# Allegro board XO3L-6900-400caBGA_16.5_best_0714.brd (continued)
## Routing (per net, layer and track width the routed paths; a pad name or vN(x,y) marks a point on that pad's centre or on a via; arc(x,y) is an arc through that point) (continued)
PR19B: length 8.2
  TOP w0.102: BGA.R20 v1(28.32,16.32)
  L3_SIGNAL w0.102: v1(28.32,16.32) 28.57,16.32 28.68,16.43 35.86,16.43
PR19C: length 12.5
  TOP w0.102: BGA.M15 v1(24.32,19.52)
  L4_SIGNAL w0.102: 35.88,19.48 27.21,19.48 26.84,19.11 24.73,19.11 v1(24.32,19.52)
PR19D: length 13.2
  TOP w0.102: BGA.M14 v1(23.52,19.52)
  L4_SIGNAL w0.102: v1(23.52,19.52) 23.92,19.92 26.97,19.92 27.22,19.66 35.89,19.66
PR21A: length 12.3
  TOP w0.102: BGA.N16 v1(25.12,18.72)
  L4_SIGNAL w0.102: 35.89,17.32 27.81,17.32 27.62,17.51 25.7,17.51 25.53,17.68 25.53,18.31 v1(25.12,18.72)
PR21B: length 9.6
  TOP w0.102: BGA.R19 v1(27.52,16.32)
  L4_SIGNAL w0.102: v1(27.52,16.32) 27.52,16.84 27.82,17.14 35.89,17.14
PR21C: length 8
  TOP w0.102: 35.88,15.7 28.39,15.7 28.17,15.92 BGA.T20
PR21D: length 8.9
  TOP w0.102: BGA.T19 27.39,15.92 27.79,15.53 35.88,15.53
PR22A: length 8.2
  TOP w0.102: BGA.U20 v1(28.32,14.72)
  L3_SIGNAL w0.102: v1(28.32,14.72) 28.7,14.72 28.8,14.61 35.86,14.61
PR22B: length 13.8
  TOP w0.102: BGA.P17 v1(25.92,17.92)
  L3_SIGNAL w0.102: v1(25.92,17.92) 25.92,17.69 26.32,17.3 26.32,14.51 26.5,14.32 28.69,14.32 28.8,14.44 35.86,14.44
PR22C: length 10
  TOP w0.102: BGA.T18 v1(26.72,15.52)
  L3_SIGNAL w0.102: v1(26.72,15.52) 26.99,15.25 27.13,15.25 27.49,15.61 35.86,15.61
PR22D: length 9.8
  TOP w0.102: BGA.U19 v1(27.52,14.72)
  L3_SIGNAL w0.102: v1(27.52,14.72) 27.25,14.99 27.25,15.13 27.56,15.44 35.86,15.44
PR23A: length 10.2
  TOP w0.102: BGA.V20 v1(28.32,13.92)
  L4_SIGNAL w0.102: 27.31,4.75 27.31,12.91 v1(28.32,13.92)
PR23B: length 14.8
  TOP w0.102: BGA.P16 v1(25.12,17.92)
  L4_SIGNAL w0.102: 27.13,4.75 27.13,12.89 26.32,13.71 26.32,15.62 26.02,15.92 25.71,15.92 25.53,16.11 25.53,17.25 25.12,17.66 v1(25.12,17.92)
PR23C: length 12.4
  TOP w0.102: BGA.N15 v1(24.32,18.72)
  BOTTOM w0.102: 35.88,18.06 28.83,18.06 28.57,18.32 24.72,18.32 v1(24.32,18.72)
PR23D: length 13.9
  TOP w0.102: BGA.N14 v1(23.52,18.72)
  BOTTOM w0.102: v1(23.52,18.72) 23.93,18.31 23.93,17.7 24.12,17.52 28.48,17.52 28.83,17.87 35.88,17.87
PR24A: length 11.4
  TOP w0.102: BGA.R17 v1(25.92,17.12)
  L4_SIGNAL w0.102: 35.89,15.88 26.58,15.88 26.32,16.15 26.32,16.72 v1(25.92,17.12)
PR24B: length 10.3
  TOP w0.102: BGA.U18 v1(26.72,14.72)
  L4_SIGNAL w0.102: 35.89,15.71 27.41,15.71 27.22,15.52 27.22,15.22 v1(26.72,14.72)
PR24C: length 14
  TOP w0.102: BGA.P15 v1(24.32,17.92)
  L4_SIGNAL w0.102: 24.23,4.75 24.23,14.19 23.91,14.51 23.91,17.51 v1(24.32,17.92)
PR24D: length 13.2
  TOP w0.102: BGA.R16 v1(25.12,17.12)
  L4_SIGNAL w0.102: 24.41,4.75 24.41,14.19 24.72,14.5 24.72,16.72 v1(25.12,17.12)
PR25A: length 10.7
  TOP w0.102: BGA.V19 v1(27.52,13.92)
  L3_SIGNAL w0.102: v1(27.52,13.92) 26.98,13.38 26.34,13.38 26.23,13.28 26.23,4.75
PR25B: length 12.5
  TOP w0.102: BGA.T17 v1(25.92,16.32)
  L3_SIGNAL w0.102: v1(25.92,16.32) 25.53,15.93 25.53,13.91 26.06,13.38 26.06,4.75
PR25C: length 11.6
  TOP w0.102: BGA.U17 v1(25.92,15.52)
  L4_SIGNAL w0.102: v1(25.92,15.52) 25.52,15.13 25.52,14.38 25.66,14.25 25.66,4.75
PR25D: length 10.6
  TOP w0.102: BGA.V17 v1(25.92,14.72)
  L4_SIGNAL w0.102: v1(25.92,14.72) 25.92,14.34 25.84,14.26 25.84,4.75
PT9A: length 8.9
  TOP w0.102: BGA.B1 12.72,27.39 12.33,27.79 12.33,35.88
PT9B: length 8
  TOP w0.102: 12.5,35.88 12.5,28.39 12.72,28.17 BGA.A1
PT9C: length 13.2
  TOP w0.102: BGA.G7 v1(17.12,23.52)
  L4_SIGNAL w0.102: v1(17.12,23.52) 16.73,23.91 16.73,27.1 17.02,27.4 17.02,35.86
PT9D: length 12.4
  TOP w0.102: BGA.F7 v1(17.12,24.32)
  L4_SIGNAL w0.102: 17.2,35.86 17.2,27.38 17.53,27.05 17.53,24.73 v1(17.12,24.32)
PT10A: length 8.9
  TOP w0.102: BGA.B2 13.52,27.39 13.13,27.79 13.13,35.88
PT10B: length 8
  TOP w0.102: 13.3,35.88 13.3,28.39 13.52,28.17 BGA.A2
PT10C: length 11.6
  TOP w0.102: BGA.E6 v1(16.32,25.12)
  L3_SIGNAL w0.102: 15.61,35.86 15.61,27.35 15.92,27.04 15.92,25.52 v1(16.32,25.12)
PT10D: length 10.8
  TOP w0.102: BGA.D5 v1(15.52,25.92)
  L3_SIGNAL w0.102: v1(15.52,25.92) 15.12,26.32 15.12,27.03 15.44,27.35 15.44,35.86
PT11A: length 8.9
  TOP w0.102: 13.93,35.88 13.93,27.79 14.32,27.39 BGA.B3
PT11B: length 8
  TOP w0.102: 14.1,35.88 14.1,28.39 14.32,28.17 BGA.A3
PT11C: length 10.8
  TOP w0.102: BGA.D6 v1(16.32,25.92)
  BOTTOM w0.102: v1(16.32,25.92) 15.92,26.32 15.92,26.99 16.22,27.28 16.22,35.86
PT11D: length 11.6
  TOP w0.102: BGA.E7 v1(17.12,25.12)
  BOTTOM w0.102: 16.4,35.86 16.4,27.27 16.72,26.95 16.72,25.52 v1(17.12,25.12)
PT12A: length 8.9
  TOP w0.102: 14.73,35.88 14.73,27.79 15.12,27.39 BGA.B4
PT12B: length 8
  TOP w0.102: BGA.A4 15.12,28.17 14.9,28.39 14.9,35.88
PT12C: length 9.8
  TOP w0.102: BGA.C6 v1(16.32,26.72)
  L3_SIGNAL w0.102: v1(16.32,26.72) 16.32,27.06 16.43,27.17 16.43,35.89
PT12D: length 10.7
  TOP w0.102: BGA.D7 v1(17.12,25.92)
  L3_SIGNAL w0.102: 16.6,35.89 16.6,27.16 16.73,27.04 16.73,26.31 v1(17.12,25.92)
PT13A: length 8.9
  TOP w0.102: 15.53,35.88 15.53,27.79 15.92,27.39 BGA.B5
PT13B: length 8
  TOP w0.102: BGA.A5 15.92,28.17 15.7,28.39 15.7,35.88
PT13C: length 13.2
  TOP w0.102: BGA.G8 v1(17.92,23.52)
  BOTTOM w0.102: 17.86,35.88 17.86,27.24 17.53,26.91 17.53,23.91 v1(17.92,23.52)
PT13D: length 12.4
  TOP w0.102: BGA.F8 v1(17.92,24.32)
  BOTTOM w0.102: 18.04,35.88 18.04,27.23 18.32,26.95 18.32,24.72 v1(17.92,24.32)
PT14A: length 8.9
  TOP w0.102: BGA.B6 16.72,27.39 16.33,27.79 16.33,35.88
PT14B: length 8
  TOP w0.102: 16.5,35.88 16.5,28.39 16.72,28.17 BGA.A6
PT14C: length 11.5
  TOP w0.102: BGA.E8 v1(17.92,25.12)
  L3_SIGNAL w0.102: v1(17.92,25.12) 17.53,25.51 17.53,35.86
PT14D: length 9.8
  TOP w0.102: BGA.C7 v1(17.12,26.72)
  L3_SIGNAL w0.102: v1(17.12,26.72) 17.12,27 17.35,27.22 17.35,35.86
PT15A: length 8.9
  TOP w0.102: 17.13,35.88 17.13,27.79 17.52,27.39 BGA.B7
PT15B: length 8
  TOP w0.102: 17.3,35.88 17.3,28.39 17.52,28.17 BGA.A7
PT15C: length 13.2
  TOP w0.102: BGA.G9 v1(18.72,23.52)
  L4_SIGNAL w0.102: 18.63,35.86 18.63,27.4 18.32,27.1 18.32,23.92 v1(18.72,23.52)
PT15D: length 12.4
  TOP w0.102: BGA.F9 v1(18.72,24.32)
  L4_SIGNAL w0.102: v1(18.72,24.32) 19.11,24.71 19.11,27.07 18.8,27.38 18.8,35.86
PT16A: length 8.9
  TOP w0.102: BGA.B8 18.32,27.39 17.93,27.79 17.93,35.88
PT16B: length 8
  TOP w0.102: 18.1,35.88 18.1,28.39 18.32,28.17 BGA.A8
PT16C: length 10.7
  TOP w0.102: BGA.D8 v1(17.92,25.92)
  L3_SIGNAL w0.102: v1(17.92,25.92) 18.31,26.31 18.31,27.04 18.21,27.13 18.21,35.86
PT16D: length 9.8
  TOP w0.102: BGA.C8 v1(17.92,26.72)
  L3_SIGNAL w0.102: 18.04,35.86 18.04,27.14 17.92,27.02 v1(17.92,26.72)
PT17A: length 8.9
  TOP w0.102: BGA.B9 19.12,27.39 18.73,27.79 18.73,35.88
PT17B: length 8
  TOP w0.102: BGA.A9 19.12,28.17 18.9,28.39 18.9,35.88
PT17C: length 9.8
  TOP w0.102: BGA.C9 v1(18.72,26.72)
  L3_SIGNAL w0.102: 18.84,35.86 18.84,27.14 18.72,27.02 v1(18.72,26.72)
PT17D: length 10.7
  TOP w0.102: BGA.D9 v1(18.72,25.92)
  L3_SIGNAL w0.102: 19.01,35.86 19.01,27.13 19.11,27.04 19.11,26.31 v1(18.72,25.92)
PT18A: length 8.9
  TOP w0.102: BGA.B10 19.92,27.39 19.53,27.79 19.53,35.88
PT18B: length 8
  TOP w0.102: 19.7,35.88 19.7,28.39 19.92,28.17 BGA.A10
PT18C: length 13.2
  TOP w0.102: BGA.G10 v1(19.52,23.52)
  L4_SIGNAL w0.102: v1(19.52,23.52) 19.52,23.73 19.85,24.06 19.85,24.63 20.19,24.97 20.19,35.83
PT18D: length 12.3
  TOP w0.102: BGA.F10 v1(19.52,24.32)
  L4_SIGNAL w0.102: 20.01,35.83 20.01,25.04 19.52,24.55 v1(19.52,24.32)
PT21A: length 8.9
  TOP w0.102: BGA.B11 20.72,27.39 20.33,27.79 20.33,35.88
PT21B: length 8
  TOP w0.102: BGA.A11 20.72,28.17 20.5,28.39 20.5,35.88
PT21C: length 10.7
  TOP w0.102: BGA.D10 v1(19.52,25.92)
  L3_SIGNAL w0.102: v1(19.52,25.92) 19.91,26.31 19.91,27.04 19.81,27.13 19.81,35.86
PT21D: length 9.8
  TOP w0.102: BGA.C10 v1(19.52,26.72)
  L3_SIGNAL w0.102: v1(19.52,26.72) 19.52,27.02 19.64,27.14 19.64,35.86
PT22A: length 8
  TOP w0.102: 21.3,35.88 21.3,28.39 21.52,28.17 BGA.A12
PT22B: length 8.9
  TOP w0.102: 21.13,35.88 21.13,27.79 21.52,27.39 BGA.B12
PT22C: length 9.8
  TOP w0.102: BGA.C11 v1(21.12,26.72)
  L3_SIGNAL w0.102: v1(21.12,26.72) 21.12,27.02 21.24,27.14 21.24,35.86
PT22D: length 10.7
  TOP w0.102: BGA.D11 v1(21.12,25.92)
  L3_SIGNAL w0.102: 21.41,35.86 21.41,27.13 21.51,27.04 21.51,26.31 v1(21.12,25.92)
PT25A: length 8
  TOP w0.102: 22.1,35.88 22.1,28.39 22.32,28.17 BGA.A13
PT25B: length 8.9
  TOP w0.102: BGA.B13 22.32,27.39 21.93,27.79 21.93,35.88
PT25C: length 13.2
  TOP w0.102: BGA.G11 v1(21.12,23.52)
  L3_SIGNAL w0.102: 20.38,35.86 20.38,25.12 20.75,24.75 20.75,24.16 21.12,23.79 v1(21.12,23.52)
PT25D: length 12.3
  TOP w0.102: BGA.F11 v1(21.12,24.32)
  L3_SIGNAL w0.102: 20.56,35.86 20.56,25.19 20.94,24.81 20.94,24.5 v1(21.12,24.32)
PT26A: length 8
  TOP w0.102: BGA.A14 23.12,28.17 22.9,28.39 22.9,35.88
PT26B: length 8.9
  TOP w0.102: BGA.B14 23.12,27.39 22.73,27.79 22.73,35.88
PT26C: length 10.7
  TOP w0.102: BGA.D12 v1(21.92,25.92)
  L3_SIGNAL w0.102: v1(21.92,25.92) 22.31,26.31 22.31,27.04 22.21,27.13 22.21,35.86
PT26D: length 9.8
  TOP w0.102: BGA.C12 v1(21.92,26.72)
  L3_SIGNAL w0.102: v1(21.92,26.72) 21.92,27.02 22.04,27.14 22.04,35.86
PT27A: length 8
  TOP w0.102: BGA.A15 23.92,28.17 23.7,28.39 23.7,35.88
PT27B: length 8.9
  TOP w0.102: BGA.B15 23.92,27.39 23.53,27.79 23.53,35.88
PT27C: length 9.8
  TOP w0.102: BGA.C13 v1(22.72,26.72)
  L3_SIGNAL w0.102: v1(22.72,26.72) 22.72,27.02 22.84,27.14 22.84,35.86
PT27D: length 10.7
  TOP w0.102: BGA.D13 v1(22.72,25.92)
  L3_SIGNAL w0.102: v1(22.72,25.92) 23.13,26.33 23.13,27.02 23.01,27.13 23.01,35.86
PT28A: length 8
  TOP w0.102: BGA.A16 24.72,28.17 24.5,28.39 24.5,35.88
PT28B: length 8.9
  TOP w0.102: BGA.B16 24.72,27.39 24.33,27.79 24.33,35.88
PT28C: length 13.5
  TOP w0.102: BGA.G12 v1(21.92,23.52)
  L4_SIGNAL w0.102: v1(21.92,23.52) 21.53,23.91 21.53,24.56 20.47,25.61 20.47,35.86
PT28D: length 12.6
  TOP w0.102: BGA.F12 v1(21.92,24.32)
  L4_SIGNAL w0.102: 20.65,35.86 20.65,25.69 21.71,24.63 21.71,24.53 v1(21.92,24.32)
PT32A: length 8
  TOP w0.102: 25.3,35.88 25.3,28.39 25.52,28.17 BGA.A17
PT32B: length 8.9
  TOP w0.102: 25.13,35.88 25.13,27.79 25.52,27.39 BGA.B17
PT32C: length 9.8
  TOP w0.102: BGA.C14 v1(23.52,26.72)
  L3_SIGNAL w0.102: v1(23.52,26.72) 23.52,27.02 23.64,27.14 23.64,35.86
PT32D: length 10.7
  TOP w0.102: BGA.D14 v1(23.52,25.92)
  L3_SIGNAL w0.102: v1(23.52,25.92) 23.91,26.31 23.91,27.04 23.81,27.13 23.81,35.86
PT33A: length 10
  TOP w0.102: BGA.C15 v1(24.32,26.72)
  L3_SIGNAL w0.102: v1(24.32,26.72) 24.53,26.72 24.63,26.82 24.63,35.86
PT33B: length 10
  TOP w0.102: BGA.C16 v1(25.12,26.72)
  L3_SIGNAL w0.102: v1(25.12,26.72) 24.91,26.72 24.81,26.82 24.81,35.86
PT33C: length 13.2
  TOP w0.102: BGA.G13 v1(22.72,23.52)
  L4_SIGNAL w0.102: v1(22.72,23.52) 22.33,23.91 22.33,26.88 22.71,27.26 22.71,35.8
PT33D: length 12.3
  TOP w0.102: BGA.F13 v1(22.72,24.32)
  L4_SIGNAL w0.102: v1(22.72,24.32) 23.12,24.72 23.12,27.01 22.89,27.25 22.89,35.8
PT34A: length 8
  TOP w0.102: BGA.A18 26.32,28.17 26.1,28.39 26.1,35.88
PT34B: length 8.9
  TOP w0.102: BGA.B18 26.32,27.39 25.93,27.79 25.93,35.88
PT34C: length 11.6
  TOP w0.102: BGA.E14 v1(23.52,25.12)
  L4_SIGNAL w0.102: 24.19,35.86 24.19,27.27 23.91,26.99 23.91,25.51 v1(23.52,25.12)
PT34D: length 10.8
  TOP w0.102: BGA.D15 v1(24.32,25.92)
  L4_SIGNAL w0.102: v1(24.32,25.92) 24.72,26.32 24.72,26.93 24.37,27.29 24.37,35.86
PT35A: length 11.6
  TOP w0.102: BGA.E15 v1(24.32,25.12)
  BOTTOM w0.102: v1(24.32,25.12) 24.72,25.52 24.72,26.85 25.03,27.16 25.03,35.88
PT35B: length 10.8
  TOP w0.102: BGA.D16 v1(25.12,25.92)
  BOTTOM w0.102: v1(25.12,25.92) 25.52,26.32 25.52,26.85 25.21,27.16 25.21,35.88
PT35C: length 13.2
  TOP w0.102: BGA.G14 v1(23.52,23.52)
  BOTTOM w0.102: 23.42,35.86 23.42,27.26 23.12,26.97 23.12,23.92 v1(23.52,23.52)
PT35D: length 12.4
  TOP w0.102: BGA.F14 v1(23.52,24.32)
  BOTTOM w0.102: 23.59,35.86 23.59,27.27 23.91,26.95 23.91,24.71 v1(23.52,24.32)
PT36A: length 8.9
  TOP w0.102: BGA.B19 27.54,27.54 27.54,35.86
PT36B: length 8
  TOP w0.102: BGA.A20 27.92,28.25 27.72,28.45 27.72,35.86
PT36C: length 9.9
  TOP w0.102: BGA.C17 v1(25.92,26.72)
  L3_SIGNAL w0.102: 26.04,35.86 26.04,27.27 26.19,27.13 26.19,26.99 v1(25.92,26.72)
PT36D: length 9.7
  TOP w0.102: BGA.A19 v1(26.72,27.52)
  L3_SIGNAL w0.102: v1(26.72,27.52) 26.45,27.25 26.31,27.25 26.22,27.35 26.22,35.86

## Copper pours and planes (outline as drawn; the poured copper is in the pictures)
GND on L2_GND: 4.78,35.93 4.78,4.71 35.93,4.71 35.93,35.93
VCC on L5_PWR: 31.59,21.56 22.27,21.56 22.27,18.31 21.56,18.31 21.56,18.93 21.44,19.04 20.13,19.04 19.85,18.76 19.85,18.47 19.75,18.38 19.14,18.38 19.14,18.94 19.28,19.08 19.58,19.08 19.88,19.38 19.88,19.95 19.14,19.95 19.14,20.66 19.86,20.66 19.86,22.27 20.78,22.27 20.78,31.81 31.59,31.81
VCCIO0 on L5_PWR: 20.69,22.36 20.69,31.81 9.16,31.81 9.16,22.36
VCCIO1 on L5_PWR: 22.37,21.45 22.37,18.21 21.55,18.21 21.55,9.28 31.6,9.28 31.6,21.45
VCCIO2 on L5_PWR: 21.4,18.93 20.18,18.93 19.95,18.71 19.95,18.43 19.79,18.28 18.31,18.28 18.31,18.9 18.12,19.08 17.53,19.08 17.53,9.28 21.45,9.28 21.45,18.88
VCCIO3 on L5_PWR: 9.15,9.28 17.43,9.28 17.43,19.18 18.16,19.18 18.41,18.94 18.41,18.38 19.04,18.38 19.04,18.98 19.24,19.18 19.53,19.18 19.77,19.42 19.77,19.85 19.04,19.85 19.04,20.26 9.15,20.26
VCCIO4 on L5_PWR: 9.15,21.46 19.77,21.46 19.77,20.76 19.04,20.76 19.04,20.37 9.15,20.37
VCCIO5 on L5_PWR: 9.16,22.26 19.77,22.26 19.77,21.56 9.16,21.56

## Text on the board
User.Comments: DM | ASP | 06/27/14 | DWG NO: | XO3L-69E-400caBGA | REVISION | 1.0 | SHEET | 1 | OF | XO3L-69C-400CABGA PCB BREAKOUT | LATTICE SEMICONDUCTOR CORPORATION
Ref Des/Silkscreen Top: PCB BREAKOUT | XO3L-69C-400CABGA | SEMICONDUCTOR | LATTICE | A | B | C | D | E | F | G | H | J | K | L | M | N | P | R | T | U | V | W | Y | 1 | 2 | 3 | 4 | 5 | 6 | 7 | 8 | 9 | 10 | 11 | 12 | 13 | 14 | 15 | 16 | 17 | 18 | 19 | 20
PAGE_OUTLINE: 1 | INITIAL RELEASE | MM/DD/YYYY | XXXX XXXXX | SPECIAL INSTRUCTIONS: | 1/2 CU OZ FOR INTERNAL AND EXTERNAL LAYERS | MIN BOARD THICKNESS IS 62MILS. | DESIGNED BY: | APPROVED BY: | SIGNATURES         DATE | REV | ESCAPE VIA DRILL | TRACE WIDTH/SPACE | ESCAPE VIA PAD | ARRAY SIZE | BGA LAND OPENING | BGA LAND PAD | PACKAGE SIZE | PITCH | DESCRIPTION | SIGNAL         (L4) | SIGNAL         (L3) | GND     PLANE  (L2) | POWER   PLANE  (L5) | PRIMARY SIDE   (L1) | SECONDARY SIDE (L6) | SECONDARY SILKSCREEN | SECONDARY SOLDERMASK | PRIMARY SOLDERMASK | PRIMARY SILKSCREEN | 0.102/0.076 | 0.8 | 0.3048 | 0.4318 | 0.3556 | 0.1524 | 17 X 17 | 20 X 20 | MM | DATE | 787.4x787.4 | 669.3x669.3 | 31.5 | 14.0 | 12.0 | 4/3 | 6.0 | 17.0 | MILS | APPROVED | PCB BREAKOUT DETAILS | 6 LAYER STACKUP | REVISION
DISPLAY_TOP: FIGURE | SIZE | 10.0 | ALL UNITS ARE IN MILS | SIZE MM | 0.254 | PLATED | QTY | 249 | DRILL CHART: TOP to BOTTOM
